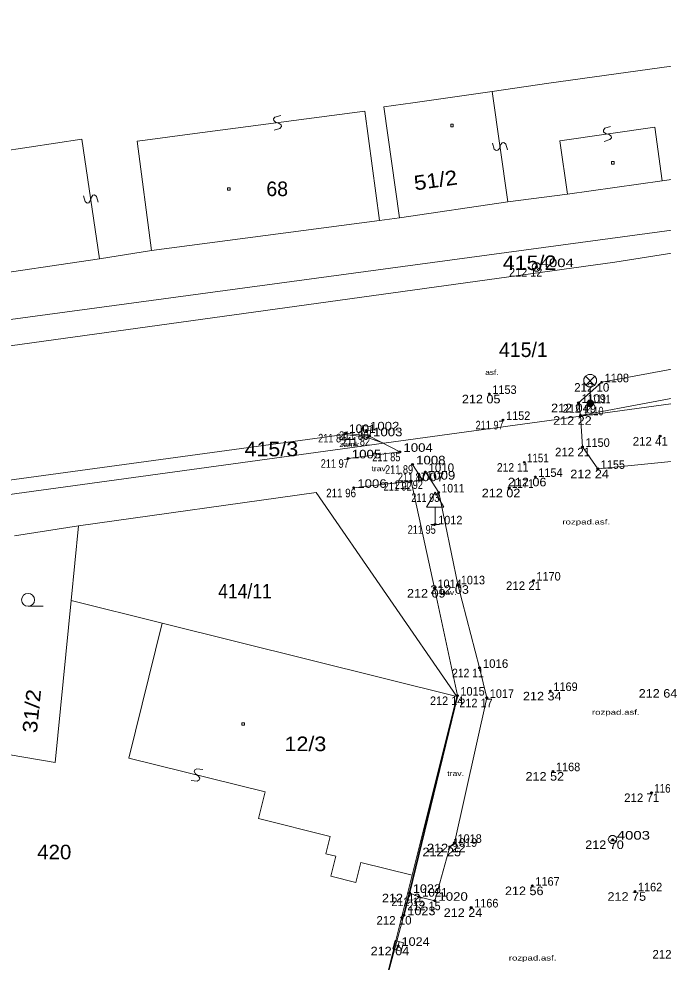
# Model space of a CAD drawing. Extents: x -736847 to -736508, y -1028413 to -1028271.
# Drawn here: x -736680.1 to -736642.6, y -1028331.6 to -1028276.6 of the extents above; entities that cross this region are included whole.
import ezdxf
from ezdxf.enums import TextEntityAlignment as Align

# ---------------------------------------------------------------- set-up
doc = ezdxf.new("R2010")
doc.units = 0
doc.header["$LTSCALE"] = 0.2
doc.header["$PDMODE"] = 32
doc.header["$PDSIZE"] = 0.1
for name, color, linetype, lineweight in [('1', 7, 'Continuous', 13), ('11', 7, 'Continuous', 13), ('13', 7, 'Continuous', 13), ('2', 7, 'Continuous', 13), ('6', 7, 'Continuous', 35), ('63', 7, 'Continuous', 13), ('8', 7, 'Continuous', 13)]:
    doc.layers.add(name, color=color, linetype=linetype, lineweight=lineweight)
for name, color, linetype in [('34', 7, 'Continuous'), ('35', 7, 'Continuous'), ('36', 7, 'Continuous'), ('60', 7, 'Continuous')]:
    doc.layers.add(name, color=color, linetype=linetype)

msp = doc.modelspace()

# ---------------------------------------------------------------- linework, layer by layer
at = {"layer": '1'}
for p, q in [((-736649.25, -1028280.31), (-736642.08, -1028279.3)), ((-736652.54, -1028280.78), (-736649.25, -1028280.31)), ((-736657.16, -1028281.44), (-736652.54, -1028280.78)), ((-736651.64, -1028287.22), (-736652.54, -1028280.78)), ((-736658.86, -1028281.68), (-736657.16, -1028281.44)), ((-736670.17, -1028283.28), (-736659.96, -1028281.94)), ((-736659.96, -1028281.94), (-736659.12, -1028288.32)), ((-736657.95, -1028288.15), (-736658.86, -1028281.68)), ((-736648.59, -1028283.66), (-736643.07, -1028282.87)), ((-736643.07, -1028282.87), (-736642.63, -1028286)), ((-736679.54, -1028284.04), (-736676.46, -1028283.57)), ((-736676.46, -1028283.57), (-736675.43, -1028290.55)), ((-736672.78, -1028283.63), (-736673.25, -1028283.69)), ((-736673.25, -1028283.69), (-736672.4, -1028290.07)), ((-736672.78, -1028283.63), (-736670.17, -1028283.28)), ((-736648.15, -1028286.77), (-736648.59, -1028283.66)), ((-736679.54, -1028284.04), (-736682.37, -1028284.46)), ((-736748.87, -1028303.31), (-736632.81, -1028287.63)), ((-736676.66, -1028306.12), (-736680.4, -1028306.7)), ((-736657.21, -1028326.51), (-736654.6, -1028316.08)), ((-736657.21, -1028326.51), (-736660.48, -1028339.57))]:
    msp.add_line(p, q, dxfattribs=at)
for points in [[(-736847.11, -1028304.1), (-736847.14, -1028305.98), (-736789.15, -1028305.56), (-736765.17, -1028304.89), (-736752.25, -1028304.39), (-736741.06, -1028303.76), (-736733.02, -1028303.04), (-736717.19, -1028301.44), (-736705.39, -1028300.01), (-736699.76, -1028298.26), (-736645.39, -1028290.74), (-736606.84, -1028284.63), (-736586.11, -1028282.62), (-736567.68, -1028281.15), (-736549.73, -1028280.36), (-736529.75, -1028279.79), (-736523.28, -1028279.48), (-736516.84, -1028278.77), (-736513.8, -1028278.17), (-736508.09, -1028276.55)], [(-736694.09, -1028293.26), (-736690.18, -1028292.72), (-736675.43, -1028290.55), (-736672.4, -1028290.07), (-736659.12, -1028288.32), (-736657.95, -1028288.15), (-736651.64, -1028287.22), (-736648.15, -1028286.77), (-736642.63, -1028286), (-736641.29, -1028285.81)], [(-736617.32, -1028295.6), (-736658.87, -1028301.31), (-736705.21, -1028307.67), (-736744.41, -1028313.05)], [(-736705.21, -1028307.67), (-736705.02, -1028307.05), (-736704.37, -1028306.69), (-736661.17, -1028300.8), (-736659.94, -1028300.93), (-736658.87, -1028301.31)], [(-736677.09, -1028310.49), (-736676.66, -1028306.12), (-736662.81, -1028304.19), (-736654.6, -1028316.08)], [(-736685.01, -1028334.2), (-736682.5, -1028319.17), (-736678.02, -1028319.93), (-736677.09, -1028310.49)], [(-736654.6, -1028316.08), (-736671.78, -1028311.81), (-736677.09, -1028310.49)], [(-736657.21, -1028326.51), (-736660.2, -1028325.77), (-736660.49, -1028326.93), (-736661.95, -1028326.57), (-736661.66, -1028325.4), (-736662.24, -1028325.26), (-736661.99, -1028324.24), (-736666.16, -1028323.2), (-736665.78, -1028321.65), (-736673.73, -1028319.67), (-736671.78, -1028311.81)]]:
    msp.add_lwpolyline(points, dxfattribs=at)
at = {"layer": '11'}
for p, q in [((-736649.985, -1028291.03), (-736649.935, -1028291.03)), ((-736645.545, -1028324.43), (-736645.495, -1028324.43))]:
    msp.add_line(p, q, dxfattribs=at)
for points in [[(-736649.885, -1028290.79), (-736649.76, -1028290.88), (-736649.71, -1028291.025), (-736649.76, -1028291.17), (-736649.885, -1028291.26), (-736650.04, -1028291.26), (-736650.165, -1028291.17), (-736650.215, -1028291.025), (-736650.165, -1028290.88), (-736650.04, -1028290.79)], [(-736645.445, -1028324.19), (-736645.32, -1028324.28), (-736645.27, -1028324.425), (-736645.32, -1028324.57), (-736645.445, -1028324.66), (-736645.6, -1028324.66), (-736645.725, -1028324.57), (-736645.775, -1028324.425), (-736645.725, -1028324.28), (-736645.6, -1028324.19)]]:
    msp.add_lwpolyline(points, close=True, dxfattribs=at)
at = {"layer": '13'}
msp.add_line((-736657.93, -1028301.81), (-736660.94, -1028302.19), dxfattribs=at)
msp.add_lwpolyline([(-736631.5, -1028297.29), (-736631.32, -1028296.29), (-736631.34, -1028295.46), (-736638.73, -1028296.37), (-736646.16, -1028297.75), (-736647.51, -1028298.95), (-736647.39, -1028299.68), (-736639.12, -1028298.14)], close=True, dxfattribs=at)
for points in [[(-736647.39, -1028299.68), (-736647.28, -1028301.52), (-736646.39, -1028302.8), (-736640.56, -1028302.22), (-736640.56, -1028302.22), (-736635.31, -1028301.59), (-736635.3, -1028303.13)], [(-736661.09, -1028300.71), (-736659.7, -1028300.9), (-736657.93, -1028301.81)], [(-736657.19, -1028302.54), (-736656.62, -1028303.43), (-736656.44, -1028302.98), (-736655.66, -1028304.18), (-736654.55, -1028309.54), (-736653.28, -1028314.41), (-736652.86, -1028316.16), (-736654.74, -1028324.62), (-736655.01, -1028324.85), (-736655.89, -1028328), (-736656.82, -1028327.76), (-736657.37, -1028327.54)]]:
    msp.add_lwpolyline(points, dxfattribs=at)
at = {"layer": '2'}
msp.add_line((-736679.6, -1028310.82), (-736678.725, -1028310.82), dxfattribs=at)
for points in [[(-736664.869, -1028282.18), (-736665.209, -1028282.275), (-736665.295, -1028282.388), (-736665.282, -1028282.487), (-736665.17, -1028282.573), (-736664.959, -1028282.646), (-736664.847, -1028282.732), (-736664.834, -1028282.831), (-736664.92, -1028282.944), (-736665.26, -1028283.039)], [(-736645.639, -1028282.833), (-736645.978, -1028282.932), (-736646.063, -1028283.045), (-736646.049, -1028283.144), (-736645.936, -1028283.229), (-736645.723, -1028283.3), (-736645.61, -1028283.385), (-736645.596, -1028283.484), (-736645.681, -1028283.597), (-736646.02, -1028283.696)], [(-736651.659, -1028284.192), (-736651.757, -1028283.852), (-736651.87, -1028283.767), (-736651.969, -1028283.781), (-736652.054, -1028283.894), (-736652.125, -1028284.105), (-736652.21, -1028284.218), (-736652.309, -1028284.232), (-736652.422, -1028284.147), (-736652.52, -1028283.807)], [(-736675.512, -1028287.248), (-736675.613, -1028286.909), (-736675.726, -1028286.825), (-736675.825, -1028286.84), (-736675.91, -1028286.953), (-736675.979, -1028287.166), (-736676.064, -1028287.279), (-736676.163, -1028287.294), (-736676.276, -1028287.21), (-736676.377, -1028286.871)], [(-736669.415, -1028320.332), (-736669.767, -1028320.296), (-736669.888, -1028320.369), (-736669.912, -1028320.466), (-736669.839, -1028320.587), (-736669.67, -1028320.732), (-736669.597, -1028320.853), (-736669.621, -1028320.95), (-736669.742, -1028321.023), (-736670.094, -1028320.987)]]:
    msp.add_lwpolyline(points, dxfattribs=at)
for points in [[(-736654.96, -1028282.69), (-736654.81, -1028282.69), (-736654.81, -1028282.84), (-736654.96, -1028282.84)], [(-736645.59, -1028284.88), (-736645.44, -1028284.88), (-736645.44, -1028285.03), (-736645.59, -1028285.03)], [(-736667.97, -1028286.4), (-736667.82, -1028286.4), (-736667.82, -1028286.55), (-736667.97, -1028286.55)], [(-736667.13, -1028317.61), (-736666.98, -1028317.61), (-736666.98, -1028317.76), (-736667.13, -1028317.76)]]:
    msp.add_lwpolyline(points, close=True, dxfattribs=at)
msp.add_circle((-736679.6, -1028310.445), 0.375, dxfattribs=at)
at = {"layer": '34'}
for p in [(-736649.96, -1028291.03), (-736646.16, -1028297.75), (-736652.71, -1028298.43), (-736647.51, -1028298.95), (-736646.83, -1028298.98), (-736647.39, -1028299.68), (-736651.91, -1028299.95), (-736661.09, -1028300.71), (-736659.88, -1028300.56), (-736659.7, -1028300.9), (-736642.75, -1028300.89), (-736657.93, -1028301.81), (-736647.28, -1028301.52), (-736660.94, -1028302.19), (-736657.19, -1028302.54), (-736650.67, -1028302.42), (-736656.44, -1028302.98), (-736646.39, -1028302.8), (-736657.27, -1028303.52), (-736656.62, -1028303.43), (-736650.03, -1028303.27), (-736660.62, -1028303.91), (-736655.66, -1028304.18), (-736651.55, -1028303.91), (-736655.87, -1028306.04), (-736654.55, -1028309.54), (-736650.14, -1028309.32), (-736655.91, -1028309.76), (-736653.28, -1028314.41), (-736649.15, -1028315.76), (-736654.57, -1028316.03), (-736652.86, -1028316.16), (-736649, -1028320.44), (-736643.25, -1028321.69), (-736645.52, -1028324.43), (-736655.01, -1028324.85), (-736654.74, -1028324.62), (-736650.2, -1028327.12), (-736657.37, -1028327.54), (-736656.82, -1028327.76), (-736644.22, -1028327.45), (-736655.89, -1028328), (-736653.77, -1028328.39), (-736657.69, -1028328.84), (-736658.03, -1028330.63)]:
    msp.add_point(p, dxfattribs=at)
at = {"layer": '6'}
msp.add_lwpolyline([(-736654.57, -1028316.03), (-736657.37, -1028327.54), (-736657.69, -1028328.84)], dxfattribs=at)
at = {"layer": '63'}
for p, q in [((-736646.58, -1028297.93), (-736647.095, -1028297.39)), ((-736647.09, -1028297.92), (-736646.565, -1028297.39))]:
    msp.add_line(p, q, dxfattribs=at)
for points in [[(-736646.83, -1028298.795), (-736646.83, -1028298.017), (-736646.927, -1028298.017), (-736647.09, -1028297.92), (-736647.192, -1028297.752), (-736647.192, -1028297.558), (-736647.095, -1028297.39), (-736646.927, -1028297.293), (-736646.733, -1028297.293), (-736646.565, -1028297.39), (-736646.468, -1028297.558), (-736646.468, -1028297.752), (-736646.58, -1028297.93), (-736646.733, -1028298.017), (-736646.83, -1028298.017)], [(-736646.83, -1028298.795), (-736646.753, -1028298.795), (-736646.645, -1028298.903), (-736646.645, -1028299.056), (-736646.753, -1028299.165), (-736646.906, -1028299.165), (-736647.015, -1028299.056), (-736647.015, -1028298.903), (-736646.906, -1028298.795), (-736646.83, -1028298.795), (-736646.753, -1028298.815), (-736646.902, -1028298.816), (-736646.93, -1028298.84), (-736646.73, -1028298.84), (-736646.69, -1028298.88), (-736646.97, -1028298.88), (-736646.991, -1028298.919), (-736646.668, -1028298.92), (-736646.669, -1028298.96), (-736646.992, -1028298.961), (-736646.991, -1028299), (-736646.667, -1028299.002), (-736646.667, -1028299.04), (-736646.989, -1028299.04), (-736646.97, -1028299.08), (-736646.69, -1028299.08), (-736646.73, -1028299.12), (-736646.93, -1028299.12), (-736646.907, -1028299.141), (-736646.75, -1028299.141)], [(-736660.127, -1028300.526), (-736660.093, -1028300.278), (-736659.598, -1028300.346), (-736659.666, -1028300.841), (-736660.161, -1028300.773), (-736660.127, -1028300.526), (-736659.632, -1028300.593)], [(-736658.095, -1028330.871), (-736658.336, -1028330.805), (-736658.205, -1028330.323), (-736657.723, -1028330.454), (-736657.854, -1028330.936), (-736658.095, -1028330.871), (-736657.964, -1028330.388)]]:
    msp.add_lwpolyline(points, dxfattribs=at)
at = {"layer": '8'}
for p, q in [((-736656.12, -1028306.04), (-736655.62, -1028306.04)), ((-736657.69, -1028328.84), (-736658.57, -1028332.09))]:
    msp.add_line(p, q, dxfattribs=at)
for points in [[(-736660.62, -1028303.91), (-736657.27, -1028303.52), (-736655.91, -1028309.76), (-736654.57, -1028316.03)], [(-736655.87, -1028306.04), (-736655.87, -1028305.04), (-736655.37, -1028305.04), (-736655.87, -1028304.165), (-736656.37, -1028305.04), (-736655.87, -1028305.04)]]:
    msp.add_lwpolyline(points, dxfattribs=at)

# ---------------------------------------------------------------- texts
at = {"layer": '2', "width": 1.15}
for s, rotation, p in [('51/2', 8.105, (-736657.04, -1028286.56)), ('31/2', 84.376, (-736679.09, -1028318.24))]:
    msp.add_text(s, height=0.85, rotation=rotation, dxfattribs=at).set_placement(p)
at = {"layer": '2'}
for s, p in [('68', (-736665.71, -1028286.89)), ('415/1', (-736652.147, -1028296.277))]:
    msp.add_text(s, height=0.85, dxfattribs=at).set_placement(p)
for s, width, p in [('415/2', 1.1, (-736651.931, -1028291.205)), ('415/3', 1.1, (-736666.981, -1028302.067)), ('414/11', 0.9, (-736668.52, -1028310.36)), ('12/3', 1.1, (-736664.65, -1028319.27)), ('420', 1.05, (-736679.07, -1028325.58))]:
    msp.add_text(s, height=0.85, dxfattribs=dict(at, width=width)).set_placement(p)
at = {"layer": '35'}
for s, width, p in [(' 4004', 1.3, (-736649.96, -1028291.03)), (' 1108', 0.95, (-736646.16, -1028297.75)), (' 1153', 0.95, (-736652.71, -1028298.43)), (' 1109', 0.95, (-736647.51, -1028298.95)), (' 1111', 0.7, (-736646.83, -1028298.98)), (' 1110', 0.8, (-736647.39, -1028299.68)), (' 1152', 0.95, (-736651.91, -1028299.95)), (' 1001', 1.05, (-736661.09, -1028300.71)), (' 1002', 1.15, (-736659.88, -1028300.56)), (' 1003', 1.15, (-736659.7, -1028300.9)), (' 1004', 1.15, (-736657.93, -1028301.81)), (' 1150', 0.95, (-736647.28, -1028301.52)), (' 1005', 1.15, (-736660.94, -1028302.19)), (' 1151', 0.85, (-736650.67, -1028302.42)), (' 1008', 1.15, (-736657.19, -1028302.54)), (' 1155', 0.95, (-736646.39, -1028302.8)), (' 1007', 1.15, (-736657.27, -1028303.52)), (' 1009', 1.15, (-736656.62, -1028303.43)), (' 1154', 0.95, (-736650.03, -1028303.27)), (' 1006', 1.15, (-736660.62, -1028303.91)), (' 1171', 0.85, (-736651.55, -1028303.91)), (' 1011', 0.9, (-736655.66, -1028304.18)), (' 1012', 0.95, (-736655.87, -1028306.04)), (' 1013', 0.95, (-736654.55, -1028309.54)), (' 1170', 0.95, (-736650.14, -1028309.32)), (' 1014', 0.95, (-736655.91, -1028309.76)), (' 1015', 0.95, (-736654.57, -1028316.03)), (' 1017', 0.95, (-736652.86, -1028316.16)), (' 1169', 0.95, (-736649.15, -1028315.76)), (' 1168', 0.95, (-736649, -1028320.44)), (' 1161', 0.85, (-736643.25, -1028321.69)), (' 4003', 1.3, (-736645.52, -1028324.43)), (' 1019', 0.95, (-736655.01, -1028324.85)), (' 1018', 0.95, (-736654.74, -1028324.62)), (' 1167', 0.95, (-736650.2, -1028327.12)), (' 1022', 1.1, (-736657.37, -1028327.54)), (' 1162', 0.95, (-736644.22, -1028327.45)), (' 1020', 1.15, (-736655.89, -1028328)), (' 1023', 1.1, (-736657.69, -1028328.84)), (' 1166', 0.95, (-736653.77, -1028328.39)), (' 1024', 1.1, (-736658.03, -1028330.63))]:
    msp.add_text(s, height=0.5, dxfattribs=dict(at, width=width)).set_placement(p)
for s, p in [(' 1010', (-736656.44, -1028302.98)), (' 1016', (-736653.28, -1028314.41)), (' 1021', (-736656.82, -1028327.76))]:
    msp.add_text(s, height=0.5, dxfattribs=at).set_placement(p)
at = {"layer": '36'}
for s, width, p in [('212 12', 0.95, (-736651.56, -1028291.58)), ('212 05', 1.1, (-736654.31, -1028298.98)), ('212 04', 1.1, (-736649.11, -1028299.5)), ('212 19', 0.95, (-736648.43, -1028299.53)), ('212 22', 1.1, (-736648.99, -1028300.23)), ('211 97', 0.8, (-736653.51, -1028300.5)), ('211 84', 0.8, (-736662.69, -1028301.26)), ('211 80', 0.85, (-736661.48, -1028301.11)), ('211 82', 0.8, (-736661.3, -1028301.45)), ('211 85', 0.8, (-736659.53, -1028302.36)), ('211 97', 0.8, (-736662.54, -1028302.74)), ('212 11', 0.9, (-736652.27, -1028302.97)), ('211 89', 0.8, (-736658.79, -1028303.09)), ('211 87', 0.8, (-736658.04, -1028303.53)), ('212 24', 1.1, (-736647.99, -1028303.35)), ('211 92', 0.8, (-736658.87, -1028304.07)), ('211 92', 0.8, (-736658.22, -1028303.98)), ('212 06', 1.1, (-736651.63, -1028303.82)), ('211 96', 0.85, (-736662.22, -1028304.46)), ('212 02', 1.1, (-736653.15, -1028304.46)), ('211 93', 0.8, (-736657.26, -1028304.73)), ('211 95', 0.8, (-736657.47, -1028306.59)), ('212 03', 1.1, (-736656.15, -1028310.09)), ('212 09', 1.1, (-736657.51, -1028310.31)), ('212 11', 0.9, (-736654.88, -1028314.96)), ('212 64', 1.1, (-736644, -1028316.15)), ('212 14', 0.95, (-736656.17, -1028316.58)), ('212 17', 0.95, (-736654.46, -1028316.71)), ('212 34', 1.1, (-736650.75, -1028316.31)), ('212 52', 1.1, (-736650.6, -1028320.99)), ('212 70', 1.1, (-736647.12, -1028324.98)), ('212 25', 1.1, (-736656.61, -1028325.4)), ('212 22', 1.1, (-736656.34, -1028325.17)), ('212 56', 1.1, (-736651.8, -1028327.67)), ('212 42', 1.1, (-736658.97, -1028328.09)), ('212 15', 0.95, (-736658.42, -1028328.31)), ('212 75', 1.1, (-736645.82, -1028328)), ('212 15', 0.95, (-736657.49, -1028328.55)), ('212 24', 1.1, (-736655.37, -1028328.94)), ('212 04', 1.1, (-736659.63, -1028331.18))]:
    msp.add_text(s, height=0.5, dxfattribs=dict(at, width=width)).set_placement(p)
for s, p in [('212 10', (-736647.76, -1028298.3)), ('212 41', (-736644.35, -1028301.44)), ('212 21', (-736648.88, -1028302.07)), ('212 21', (-736651.74, -1028309.87)), ('212 71', (-736644.85, -1028322.24)), ('212 10', (-736659.29, -1028329.39)), ('212 91', (-736643.2, -1028331.37))]:
    msp.add_text(s, height=0.5, dxfattribs=at).set_placement(p)
at = {"layer": '60'}
for s, width, p in [('asf.', 1.2, (-736652.561, -1028297.32)), ('zamk.', 1.2, (-736660.809, -1028301.523)), ('trav.', 1.25, (-736659.091, -1028302.937)), ('rozpad.asf.', 1.4, (-736647.061, -1028306.046)), ('trav.', 1.25, (-736655.106, -1028310.158)), ('rozpad.asf.', 1.4, (-736645.338, -1028317.148)), ('trav.', 1.25, (-736654.676, -1028320.721)), ('rozpad.asf.', 1.4, (-736650.186, -1028331.484))]:
    msp.add_text(s, height=0.3, dxfattribs=dict(at, width=width)).set_placement(p, align=Align.CENTER)

doc.saveas('drawing.dxf')
